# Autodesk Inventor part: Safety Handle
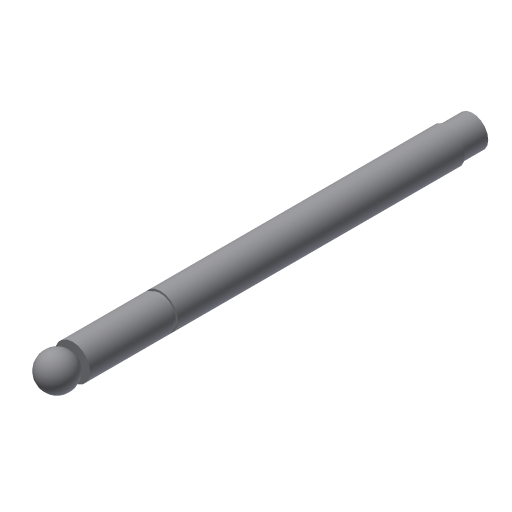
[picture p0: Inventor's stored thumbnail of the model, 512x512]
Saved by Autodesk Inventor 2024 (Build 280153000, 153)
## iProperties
Shininess: 77.0
Length Units: 11269
Angle Units: 11279
Time Units: 11290
Mass Units: 11283
Length Display Precision: 3
Angle Display Precision: 2
Created: 2002-02
Part Number: Safety Handle
Document SubType Name: Modeling
Designer: ***
Density: 1 g/cm^3
Material: Generic
Mass: 54.3914 g
Surface Area: 130.219 cm^2
Volume: 54.3914 cm^3
Appearance: Default
Density: 0.0
Volumn: 0.0
Area: 0.0
PropertySet Name: Model Information
Control State: 0
Master: False
Checked Out: False
Author: ***
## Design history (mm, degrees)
sketch "Sketch1"
  geometry: L1 (0, 205)-(8, 205); L2 (8, 205)-(8, 192); L3 (8, 192)-(9, 192); L4 (9, 192)-(9, 45); L5 (9, 45)-(8, 45); L6 (8, 45)-(8, 43); L7 (8, 43)-(9, 43); L8 (9, 43)-(9, 0); L9 (9, 0)-(0, 0); L10 (0, 0)-(0, 205)
  constraints: 20 end point, 7 parallel, 1 collinear, 1 horizontal, 1 perpendicular
  dimensions: "d0" = 13 distance of L1.end L2.end; "d1" = 2 distance of L4.end L7.end; "d2" = 43 distance of L7.end L8.end; "d3" = 205 distance of L9.end L1.start; "d4" = 16 diameter of L2 L10; "d5" = 18 diameter of L4 L10; "d6" = 16 diameter of L6.end L10
revolve "Revolution1" sketch "Sketch1" stored, may be unused: angle "d7" = 90 deg
sketch "Sketch2"
  geometry: L1 (0, 1)-(0, -17); L2 (-9, 0)-(9, 0) reference; A1 r 9 centre (0, -8) between (0, -17) and (0, 1)
  constraints: 2 end point, 2 point on circle, 1 centre point, 1 midpoint, 1 vertical
  dimensions: "d8" = 9 radius of A1; "d9" = 1 distance from line of L2 L1.start
revolve "Revolution2" sketch "Sketch2" stored, may be unused: angle "d10" = 90 deg
body "Solid1"
